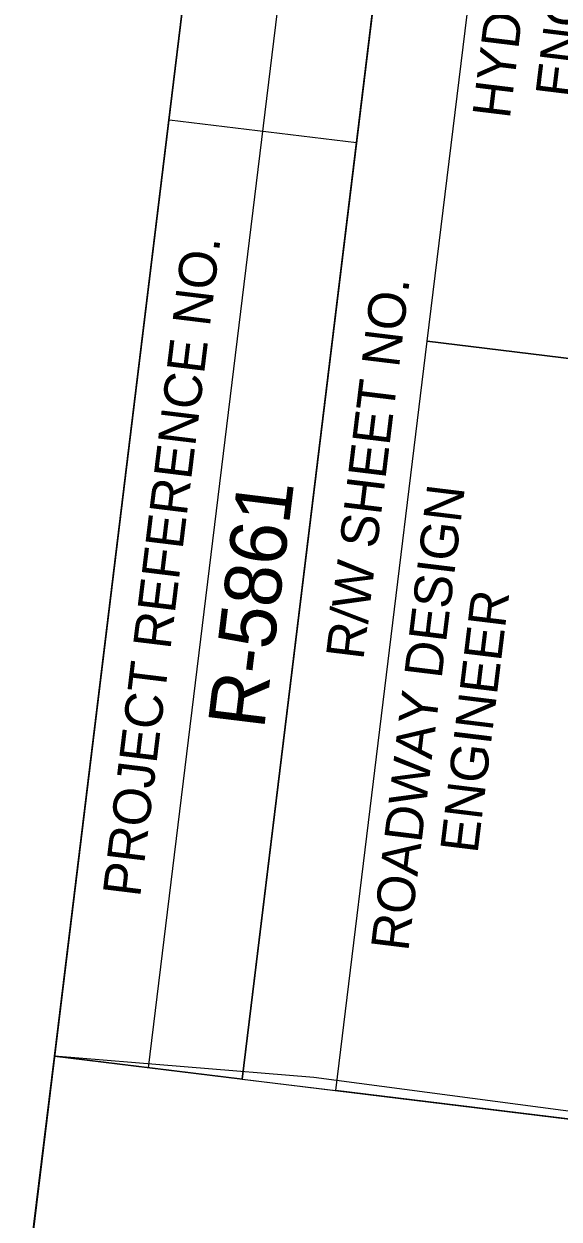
# Model space of a CAD drawing. Extents: x 480792 to 482083, y 490046 to 491850.
# Drawn here: x 480987.9 to 481058.8, y 491610.4 to 491768.8 of the extents above; entities that cross this region are included whole.
import ezdxf

# ---------------------------------------------------------------- set-up
doc = ezdxf.new("R2010")
doc.units = 0
for name, color, linetype in [('Sheet Clip Boundary CELL', 7, 'Continuous'), ('Sheet Data Field CELL', 7, 'Continuous'), ('Sheet Plan CELL', 7, 'Continuous')]:
    doc.layers.add(name, color=color, linetype=linetype)

msp = doc.modelspace()

# ---------------------------------------------------------------- linework, layer by layer
at = {"layer": 'Sheet Clip Boundary CELL'}
msp.add_lwpolyline([(480960.89, 490427.66), (481123.7, 490407.77), (481546.78, 490356.1), (481674.49, 490340.53), (481662.51, 490242.06), (481694.92, 490236.5), (481876.58, 490214.31), (482038.38, 491533.84), (481958.33, 491543.66), (481978.88, 491711.23), (481782.84, 491735.27), (481563.21, 491713.66), (481210.33, 491642.39), (481164.2, 491610.96), (481026.3, 491629.16), (480991.92, 491631.99), (480846.54, 490441.62)], close=True, dxfattribs=at)
at = {"layer": 'Sheet Plan CELL'}
for p, q in [((481004.37, 491630.45), (481028.64, 491829.02)), ((481016.82, 491628.94), (481041.05, 491827.51)), ((481016.82, 491628.94), (481041.05, 491827.51)), ((481007.15, 491756.07), (481031.97, 491753.09)), ((481041.34, 491726.74), (481152.98, 491713.12)), ((481016.82, 491628.94), (481029.21, 491627.43))]:
    msp.add_line(p, q, dxfattribs=at)
for points in [[(481016.19, 491830.58), (480834.33, 490341.61), (481876.58, 490214.31), (482058.44, 491703.26)], [(480991.92, 491631.99), (481016.19, 491830.58), (481041.05, 491827.51), (481016.82, 491628.94)], [(481041.34, 491726.74), (481053.45, 491825.99), (481165.14, 491812.37), (481153.03, 491713.1)], [(481876.58, 490214.31), (480834.35, 490341.58), (480991.92, 491631.99), (481140.87, 491613.81), (481165.14, 491812.37), (482058.44, 491703.26)], [(481029.21, 491627.43), (481041.34, 491726.74), (481153.03, 491713.1), (481140.87, 491613.81)]]:
    msp.add_lwpolyline(points, close=True, dxfattribs=at)

# ---------------------------------------------------------------- texts
at = {"layer": 'Sheet Data Field CELL'}
msp.add_text('R-5861', height=7.5, rotation=83.0365, dxfattribs=at).set_placement((481019.69, 491675.2))
at = {"layer": 'Sheet Plan CELL'}
for s, height, p in [('HYDRAULICS', 5, (481052.26, 491756.1)), ('ENGINEER', 5, (481060.62, 491758.87)), ('PROJECT REFERENCE NO.', 5.0001, (481003.27, 491652.96)), ('R/W SHEET NO.', 5.0001, (481032.85, 491684.41)), ('ROADWAY DESIGN', 5.0001, (481038.81, 491645.78)), ('ENGINEER', 5, (481047.99, 491658.75))]:
    msp.add_text(s, height=height, rotation=83.0365, dxfattribs=at).set_placement(p)

doc.saveas('drawing.dxf')
